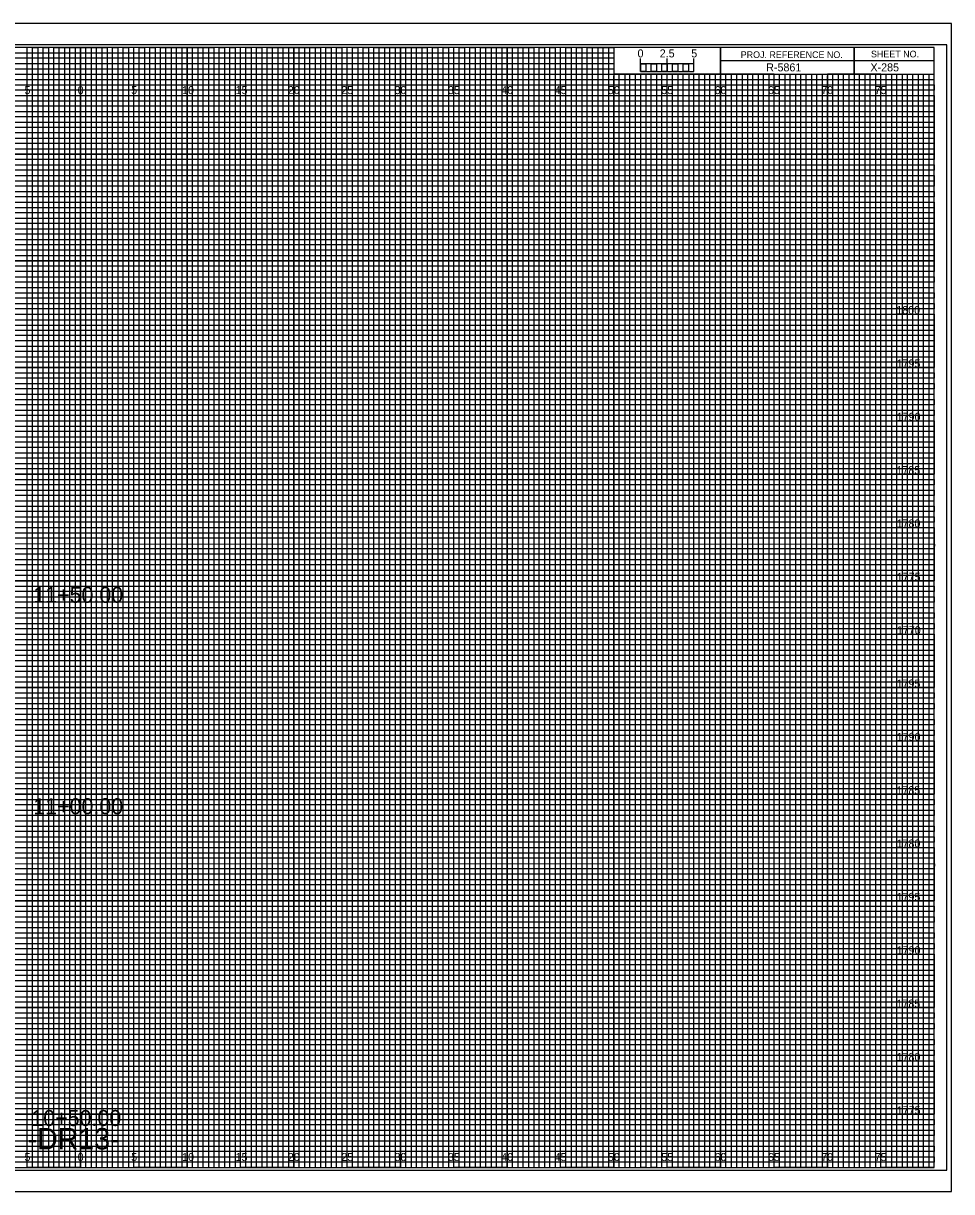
# Model space of a CAD drawing. Extents: x -7 to 162, y -2 to 107.
# Drawn here: x 74.6 to 161.7, y -2.3 to 107.3 of the extents above; entities that cross this region are included whole.
import ezdxf

# ---------------------------------------------------------------- set-up
doc = ezdxf.new("R2010")
doc.units = 0
for name, color, linetype in [('Prop XS Alignment Label', 7, 'Continuous'), ('Prop XS Bar Scale Labels', 7, 'Continuous'), ('Prop XS Elevation Labels', 7, 'Continuous'), ('Prop XS Offset Labels', 7, 'Continuous'), ('Prop XS Project Number', 7, 'Continuous'), ('Prop XS Sheet Number', 7, 'Continuous'), ('Prop XS Station Labels', 7, 'Continuous'), ('Sheet Cross Section CELL', 7, 'Continuous'), ('Sheet Cross Section Grid Major CELL', 7, 'Continuous'), ('Sheet Cross Section Grid Middle CELL', 7, 'Continuous'), ('Sheet Cross Section Grid Minor 1 CELL', 7, 'Continuous'), ('Sheet Cross Section Grid Minor 2 CELL', 7, 'Continuous'), ('Sheet Cross Section Scale CELL', 7, 'Continuous'), ('Sheet Cutting Line CELL', 7, 'Continuous'), ('Sheet DOT Grid CELL', 7, 'Continuous'), ('Sheet Plot Border Inside CELL', 7, 'Continuous'), ('Sheet Plot Border Outside CELL', 7, 'Continuous')]:
    doc.layers.add(name, color=color, linetype=linetype)

msp = doc.modelspace()

# ---------------------------------------------------------------- linework, layer by layer
at = {"layer": 'Sheet Cross Section CELL'}
for p, q in [((152.5, 105), (152.5, 102.5)), ((152.5, 102.5), (152.5, 105)), ((160, 103.75), (140, 103.75)), ((140, 103.75), (140, 102.5)), ((140, 102.5), (160, 102.5))]:
    msp.add_line(p, q, dxfattribs=at)
for points in [[(160, 105), (0, 105), (0, 0), (160, 0)], [(140, 105), (130, 105), (130, 102.52), (140, 102.52)], [(160, 105), (140, 105), (140, 102.5), (160, 102.5)]]:
    msp.add_lwpolyline(points, close=True, dxfattribs=at)
at = {"layer": 'Sheet Cross Section Grid Major CELL'}
for p, q in [((75, 105), (70, 105)), ((75, 0), (75, 105)), ((85, 105), (80, 105)), ((80, 105), (80, 0)), ((85, 0), (85, 105)), ((95, 105), (90, 105)), ((90, 105), (90, 0)), ((95, 0), (95, 105)), ((105, 105), (100, 105)), ((100, 105), (100, 0)), ((105, 0), (105, 105)), ((115, 105), (110, 105)), ((110, 105), (110, 0)), ((115, 0), (115, 105)), ((125, 105), (120, 105)), ((120, 105), (120, 0)), ((125, 0), (125, 105)), ((130, 105), (130, 0)), ((135, 0), (135, 102.5)), ((145, 102.5), (140, 102.5)), ((140, 102.5), (140, 0)), ((145, 0), (145, 102.5)), ((155, 102.5), (150, 102.5)), ((150, 102.5), (150, 0)), ((155, 0), (155, 102.5)), ((80, 0), (75, 0)), ((90, 0), (85, 0)), ((100, 0), (95, 0)), ((110, 0), (105, 0)), ((120, 0), (115, 0)), ((130, 0), (125, 0)), ((140, 0), (135, 0)), ((150, 0), (145, 0)), ((160, 0), (155, 0)), ((160, 0), (160, 0))]:
    msp.add_line(p, q, dxfattribs=at)
for points in [[(0, 100), (160, 100), (160, 95), (0, 95)], [(0, 90), (160, 90), (160, 85), (0, 85)], [(0, 80), (160, 80), (160, 75), (0, 75)], [(0, 70), (160, 70), (160, 65), (0, 65)], [(0, 60), (160, 60), (160, 55), (0, 55)], [(0, 50), (160, 50), (160, 45), (0, 45)], [(0, 40), (160, 40), (160, 35), (0, 35)], [(0, 30), (160, 30), (160, 25), (0, 25)], [(0, 20), (160, 20), (160, 15), (0, 15)], [(0, 10), (160, 10), (160, 5), (0, 5)]]:
    msp.add_lwpolyline(points, dxfattribs=at)
at = {"layer": 'Sheet Cross Section Grid Middle CELL'}
for points in [[(72.5, 0), (77.5, 0), (77.5, 105), (82.5, 105), (82.5, 0), (87.5, 0), (87.5, 105), (92.5, 105), (92.5, 0), (97.5, 0), (97.5, 105), (102.5, 105), (102.5, 0), (107.5, 0), (107.5, 105), (112.5, 105), (112.5, 0), (117.5, 0), (117.5, 105), (122.5, 105), (122.5, 0), (127.5, 0), (127.5, 105), (129.97, 105), (130, 105), (130, 102.5), (132.5, 102.5), (132.5, 0), (137.5, 0), (137.5, 102.5), (142.5, 102.5), (142.5, 0), (147.5, 0), (147.5, 102.5), (152.5, 102.5), (152.5, 0), (157.5, 0), (157.5, 102.5)], [(0, 102.5), (137.5, 102.5)], [(0, 92.5), (160, 92.5), (160, 97.5), (0, 97.5)], [(0, 82.5), (160, 82.5), (160, 87.5), (0, 87.5)], [(0, 72.5), (160, 72.5), (160, 77.5), (0, 77.5)], [(0, 62.5), (160, 62.5), (160, 67.5), (0, 67.5)], [(0, 52.5), (160, 52.5), (160, 57.5), (0, 57.5)], [(0, 42.5), (160, 42.5), (160, 47.5), (0, 47.5)], [(0, 32.5), (160, 32.5), (160, 37.5), (0, 37.5)], [(0, 22.5), (160, 22.5), (160, 27.5), (0, 27.5)], [(0, 12.5), (160, 12.5), (160, 17.5), (0, 17.5)], [(0, 2.5), (160, 2.5), (160, 7.5), (0, 7.5)]]:
    msp.add_lwpolyline(points, dxfattribs=at)
at = {"layer": 'Sheet Cross Section Grid Minor 1 CELL'}
for p, q in [((0, 104.5), (130, 104.5)), ((130, 104.5), (130, 103.99)), ((130, 103.99), (0, 103.99)), ((0, 103.5), (130, 103.5)), ((130, 102.95), (0, 102.95)), ((130, 103.5), (130, 102.95)), ((0, 102), (160, 102))]:
    msp.add_line(p, q, dxfattribs=at)
for points in [[(0, 101.5), (135, 101.5), (160, 101.5), (160, 101), (0, 101)], [(0, 100.5), (160, 100.5), (160, 99.5), (0, 99.5)], [(0, 99), (160, 99), (160, 98.5), (0, 98.49)], [(0, 98), (160, 98), (160, 97), (0, 97)], [(0, 96.5), (160, 96.5), (160, 96), (0, 96)], [(0, 95.5), (160, 95.5), (160, 94.5), (0, 94.5)], [(0, 94), (160, 94), (160, 93.5), (0, 93.5)], [(0, 93), (160, 93), (160, 92), (0, 92)], [(0, 91.5), (160, 91.5), (160, 91), (0, 91)], [(0, 90.5), (160, 90.5), (160, 89.5), (0, 89.5)], [(0, 89), (160, 89), (160, 88.5), (0, 88.5)], [(0, 88), (160, 88), (160, 86.98), (160, 86.5), (160, 86), (0, 86)], [(0, 87), (160, 87), (160, 86.5), (0, 86.5)], [(0, 85.5), (160, 85.5), (160, 84.5), (0, 84.52)], [(0, 84.52), (160, 84.5), (160, 84), (0, 84)], [(0, 83.5), (160, 83.5), (160, 83), (0, 83)], [(0, 82), (160, 82), (160, 81.5), (0, 81.5)], [(0, 81), (160, 81), (160, 80.5), (0, 80.5)], [(-0.04, 79.45), (160, 79.45), (160, 78.94), (-0.04, 78.94)], [(0, 78.5), (160, 78.5), (160, 78), (0, 78)], [(0, 77), (160, 77), (160, 76.5), (0, 76.5)], [(0, 76), (160, 76), (160, 75.5), (0, 75.5)], [(0, 74.5), (160, 74.5), (160, 74), (0, 74)], [(0, 73.5), (160, 73.5), (160, 73), (0, 73)], [(0, 72), (160, 72), (160, 71.5), (0, 71.5)], [(0, 71), (160, 71), (160, 70.5), (0, 70.5)], [(0, 69.5), (160, 69.5), (160, 68.99), (0, 69)], [(0, 68.5), (160, 68.5), (160, 68), (0, 68)], [(0, 67), (160, 67), (160, 66.5), (0, 66.5)], [(0, 66), (160, 66), (160, 65.5), (0, 65.5)], [(0, 64.5), (160, 64.5), (160, 64), (0, 64)], [(0, 63.5), (160, 63.5), (160, 63), (0, 63)], [(0, 62), (160, 62), (160, 61.5), (0, 61.5)], [(0, 61), (160, 61), (160, 60.5), (0, 60.5)], [(0, 59.5), (160, 59.5), (160, 59), (0, 59)], [(0, 58.5), (160.03, 58.45), (160, 58), (0, 58)], [(0, 57), (160, 57), (160, 56.5), (0, 56.5)], [(0, 56), (160, 56), (160, 55.5), (0, 55.5)], [(0, 54.5), (160, 54.5), (160, 54), (0, 54)], [(0, 53.5), (160, 53.5), (160, 53), (0, 53)], [(0, 52), (160, 52), (160, 51.5), (0, 51.5)], [(0, 51), (160, 51), (160, 50.5), (0, 50.5)], [(0, 49.5), (160, 49.5), (160, 49), (0, 49)], [(0, 48.5), (160, 48.5), (160, 48), (0, 48)], [(0, 47), (160, 47), (160, 46.5), (0, 46.5)], [(0, 46), (160, 46), (160, 45.5), (0, 45.5)], [(0, 44.5), (160, 44.5), (160, 44), (0, 44)], [(0, 43.5), (160, 43.5), (160, 43), (0, 43)], [(0, 42), (160, 42), (160, 41.5), (0, 41.5)], [(0, 41), (160, 41), (160, 40.5), (0, 40.5)], [(0, 39.5), (160, 39.5), (160, 38.99), (0, 39)], [(0, 38.5), (160, 38.5), (160, 38), (0, 38)], [(0, 37), (160, 37), (160, 36.5), (0, 36.5)], [(0, 36), (160, 36), (160, 35.5), (0, 35.5)], [(0, 34.5), (160, 34.5), (160, 34), (0, 34)], [(0, 33.5), (160, 33.5), (160, 33), (0, 33)], [(0, 32), (160, 32), (160, 31.5), (0, 31.5)], [(0, 31), (160, 31), (160, 30.5), (0, 30.5)], [(0, 29.5), (160, 29.5), (160, 29), (0, 29)], [(0, 28.5), (160.03, 28.46), (160, 28), (0, 28)], [(0, 27), (160, 27), (160, 26.5), (0, 26.5)], [(0, 26), (160, 26), (160, 25.5), (0, 25.5)], [(0, 24.5), (160, 24.5), (160, 24), (0, 24)], [(0, 23.5), (160, 23.5), (160, 23), (0, 23)], [(0, 22), (160, 22), (160, 21.5), (0, 21.5)], [(0, 21), (160, 21), (160, 20.5), (0, 20.5)], [(0, 19.5), (160, 19.5), (160, 19), (0, 19)], [(0, 18.5), (160, 18.5), (160, 18), (0, 18)], [(0, 17), (160, 17), (160, 16.5), (0, 16.5)], [(0, 16), (160, 16), (160, 15.5), (0, 15.5)], [(0, 14.5), (160, 14.5), (160, 14), (0, 14)], [(0, 13.5), (160, 13.5), (160, 13), (0, 13)], [(0, 12), (160, 12), (160, 11.5), (0, 11.5)], [(0, 11), (160, 11), (160, 10.5), (0, 10.5)], [(0, 9.5), (160, 9.5), (160, 9), (0, 9)], [(0, 8.5), (160, 8.5), (160, 8), (0, 8)], [(0, 7), (160, 7), (160, 6.5), (0, 6.5)], [(0, 6), (160, 6), (160, 5.5), (0, 5.5)], [(0, 4.5), (160, 4.5), (160, 4), (0, 4)], [(0, 3.5), (160, 3.5), (160, 3), (0, 3)], [(0, 2), (160, 2), (160, 1.5), (0, 1.5)], [(0, 1), (160, 1), (160, 0.5), (0, 0.5)]]:
    msp.add_lwpolyline(points, dxfattribs=at)
at = {"layer": 'Sheet Cross Section Grid Minor 2 CELL'}
for p, q in [((133.5, 102.5), (133, 102.5)), ((133, 102.5), (133, 0)), ((133.5, 0), (133.5, 102.5)), ((134.5, 102.5), (134, 102.5)), ((134, 102.5), (134, 0)), ((134.5, 0), (134.5, 102.5)), ((133, 0), (132.5, 0)), ((134, 0), (133.5, 0))]:
    msp.add_line(p, q, dxfattribs=at)
for points in [[(75, 0), (75.5, 0), (75.5, 105), (76, 105), (76, 0)], [(76, 0), (76.5, 0), (76.5, 105), (77, 105), (77, 0)], [(77.5, 0), (78, 0), (78, 105), (78.5, 105), (78.5, 0)], [(78.5, 0), (79, 0), (79, 105), (79.5, 105), (79.5, 0)], [(80, 0), (80.5, 0), (80.5, 105), (81, 105), (81, 0)], [(81, 0), (81.5, 0), (81.5, 105), (82, 105), (82, 0)], [(82.5, 0), (83, 0), (83, 105), (83.5, 105), (83.5, 0)], [(83.5, 0), (84, 0), (84, 105), (84.5, 105), (84.5, 0)], [(85, 0), (85.5, 0), (85.5, 105), (86, 105), (86, 0)], [(86, 0), (86.5, 0), (86.5, 105), (87, 105), (87, 0)], [(87.5, 0), (88, 0), (88, 105), (88.5, 105), (88.5, 0)], [(88.5, 0), (89, 0), (89, 105), (89.5, 105), (89.5, 0)], [(90, 0), (90.5, 0), (90.5, 105), (91, 105), (91, 0)], [(91, 0), (91.5, 0), (91.5, 105), (92, 105), (92, 0)], [(92.5, 0), (93, 0), (93, 105), (93.5, 105), (93.5, 0)], [(93.5, 0), (94, 0), (94, 105), (94.5, 105), (94.5, 0)], [(95, 0), (95.5, 0), (95.5, 105), (96, 105), (96, 0)], [(96, 0), (96.5, 0), (96.5, 105), (97, 105), (97, 0)], [(97.5, 0), (98, 0), (98, 105), (98.5, 105), (98.5, 0)], [(98.5, 0), (99, 0), (99, 105), (99.5, 105), (99.5, 0)], [(100, 0), (100.5, 0), (100.5, 105), (101, 105), (101, 0)], [(101, 0), (101.5, 0), (101.5, 105), (102, 105), (102, 0)], [(102.5, 0), (103, 0), (103, 105), (103.5, 105), (103.5, 0)], [(103.5, 0), (104, 0), (104, 105), (104.5, 105), (104.5, 0)], [(105, 0), (105.5, 0), (105.5, 105), (106, 105), (106, 0)], [(106, 0), (106.5, 0), (106.5, 105), (107, 105), (107, 0)], [(107.5, 0), (108, 0), (108, 105), (108.5, 105), (108.5, 0)], [(108.5, 0), (109, 0), (109, 105), (109.5, 105), (109.5, 0)], [(110, 0), (110.5, 0), (110.5, 105), (111, 105), (111, 0)], [(111, 0), (111.5, 0), (111.5, 105), (112, 105), (112, 0)], [(112.5, 0), (113, 0), (113, 105), (113.5, 105), (113.5, 0)], [(113.5, 0), (114, 0), (114, 105), (114.5, 105), (114.5, 0)], [(115, 0), (115.5, 0), (115.5, 105), (116, 105), (116, 0)], [(116, 0), (116.5, 0), (116.5, 105), (117, 105), (117, 0)], [(117.5, 0), (118, 0), (118, 105), (118.5, 105), (118.5, 0)], [(118.5, 0), (119, 0), (119, 105), (119.5, 105), (119.5, 0)], [(120, 0), (120.5, 0), (120.5, 105), (121, 105), (121, 0)], [(121, 0), (121.5, 0), (121.5, 105), (122, 105), (122, 0)], [(122.5, 0), (123, 0), (123, 105), (123.5, 105), (123.5, 0)], [(123.5, 0), (124, 0), (124, 105), (124.5, 105), (124.5, 0)], [(125, 0), (125.5, 0), (125.5, 105), (126, 105), (126, 0)], [(126, 0), (126.5, 0), (126.5, 105), (127, 105), (127, 0)], [(127.5, 0), (128, 0), (128, 105), (128.5, 105), (128.5, 0)], [(128.5, 0), (129, 0), (129, 105), (129.5, 105), (129.5, 0)], [(130, 0), (130.5, 0), (130.5, 102.5), (131.01, 102.5), (131.01, 0)], [(131, 0), (131.5, 0), (131.5, 102.5), (132, 102.5), (132, 0)], [(135, 0), (135.49, 0), (135.49, 102.5), (136, 102.5), (136, 0)], [(136, 0), (136.5, 0), (136.5, 102.5), (137.03, 102.5), (137.03, 0)], [(137.5, 0), (138, 0), (138, 102.5), (138.5, 102.5), (138.5, 0)], [(138.5, 0), (139, 0), (139, 102.5), (139.5, 102.5), (139.5, 0)], [(140, 0), (140.5, 0), (140.5, 102.5), (141, 102.5), (141, 0)], [(141, 0), (141.5, 0), (141.5, 102.5), (142, 102.5), (142, 0)], [(142.5, 0), (143, 0), (143, 102.5), (143.5, 102.5), (143.5, 0)], [(143.5, 0), (144, 0), (144, 102.5), (144.5, 102.5), (144.5, 0)], [(145, 0), (145.5, 0), (145.5, 102.5), (146, 102.5), (146, 0)], [(146, 0), (146.5, 0), (146.5, 102.5), (147, 102.5), (147, 0)], [(147.5, 0), (148, 0), (148, 102.5), (148.5, 102.5), (148.5, 0)], [(148.5, 0), (149, 0), (149, 102.5), (149.5, 102.5), (149.5, 0)], [(150, 0), (150.5, 0), (150.5, 102.5), (151, 102.5), (151, 0)], [(151, 0), (151.5, 0), (151.5, 102.5), (152, 102.5), (152, 0)], [(152.5, 0), (153, 0), (153, 102.5), (153.5, 102.5), (153.5, 0)], [(153.5, 0), (154, 0), (154, 102.5), (154.5, 102.5), (154.5, 0)], [(155, 0), (155.5, 0), (155.5, 102.5), (156, 102.5), (156, 0)], [(156, 0), (156.5, 0), (156.5, 102.5), (157, 102.5), (157, 0)], [(157.5, 0), (158, 0), (158, 102.5), (158.5, 102.5), (158.5, 0)], [(158.5, 0), (159, 0), (159, 102.5), (159.5, 102.5), (159.5, 0)]]:
    msp.add_lwpolyline(points, dxfattribs=at)
at = {"layer": 'Sheet Cross Section Scale CELL'}
for p, q in [((132.5, 102.75), (132.5, 103.95)), ((132.5, 103.45), (132.5, 103.95)), ((135, 102.75), (135, 103.95)), ((137.5, 102.75), (137.5, 103.95)), ((137.5, 103.45), (137.5, 103.95))]:
    msp.add_line(p, q, dxfattribs=at)
for points in [[(137.5, 103.45), (132.5, 103.45), (132.5, 102.75), (137.5, 102.75)], [(132.5, 103.45), (133, 103.45), (133, 102.75), (132.5, 102.75)], [(133.5, 103.45), (134, 103.45), (134, 102.75), (133.5, 102.75)], [(134.5, 103.45), (135, 103.45), (135, 102.75), (134.5, 102.75)], [(135.5, 103.45), (136, 103.45), (136, 102.75), (135.5, 102.75)], [(136.5, 103.45), (137, 103.45), (137, 102.75), (136.5, 102.75)]]:
    msp.add_lwpolyline(points, close=True, dxfattribs=at)
at = {"layer": 'Sheet Cutting Line CELL'}
for p, q in [((161.65, 107.25), (-6.7, 107.25)), ((-6.7, -2.25), (161.65, -2.25))]:
    msp.add_line(p, q, dxfattribs=at)
at = {"layer": 'Sheet DOT Grid CELL'}
for p, q in [((75, 0), (75, 105)), ((80, 0), (80, 105)), ((85, 0), (85, 105)), ((90, 0), (90, 105)), ((95, 0), (95, 105)), ((100, 0), (100, 105)), ((105, 0), (105, 105)), ((110, 0), (110, 105)), ((115, 0), (115, 105)), ((120, 0), (120, 105)), ((125, 0), (125, 105)), ((130, 0), (130, 102.34)), ((135, 0), (135, 102.34)), ((140, 0), (140, 102.34)), ((145, 0), (145, 102.34)), ((150, 0), (150, 102.34)), ((155, 0), (155, 102.34)), ((0, 100), (160, 100)), ((0, 95), (160, 95)), ((0, 90), (160, 90)), ((0, 85), (160, 85)), ((0, 80), (160, 80)), ((0, 75), (160, 75)), ((0, 70), (160, 70)), ((0, 65), (160, 65)), ((0, 60), (160, 60)), ((0, 55), (160, 55)), ((0, 50), (160, 50)), ((0, 45), (160, 45)), ((0, 40), (160, 40)), ((0, 35), (160, 35)), ((0, 30), (160, 30)), ((0, 25), (160, 25)), ((0, 20), (160, 20)), ((0, 15), (160, 15)), ((0, 10), (160, 10)), ((0, 5), (160, 5))]:
    msp.add_line(p, q, dxfattribs=at)
at = {"layer": 'Sheet Plot Border Inside CELL'}
msp.add_lwpolyline([(-5.4, -0.25), (161.2, -0.25), (161.2, 105.25), (-5.4, 105.25)], close=True, dxfattribs=at)
at = {"layer": 'Sheet Plot Border Outside CELL'}
msp.add_lwpolyline([(-6.7, -2.25), (161.65, -2.25), (161.65, 107.25), (-6.7, 107.25)], close=True, dxfattribs=at)

# ---------------------------------------------------------------- texts
at = {"layer": 'Prop XS Alignment Label'}
msp.add_text('-DR13-', height=2, dxfattribs=at).set_placement((75.04, 1.71))
at = {"layer": 'Prop XS Bar Scale Labels'}
for s, p in [('2.5', (134.29, 104.06)), ('5', (137.24, 104.06))]:
    msp.add_text(s, height=0.75, dxfattribs=at).set_placement(p)
at = {"layer": 'Prop XS Elevation Labels'}
for s, p in [('1800', (156.46, 80)), ('1795', (156.49, 75)), ('1790', (156.5, 70)), ('1785', (156.48, 65)), ('1780', (156.49, 60)), ('1775', (156.51, 55)), ('1770', (156.52, 50)), ('1795', (156.49, 45)), ('1790', (156.5, 40)), ('1785', (156.48, 35)), ('1780', (156.49, 30)), ('1795', (156.49, 25)), ('1790', (156.5, 20)), ('1785', (156.48, 15)), ('1780', (156.49, 10)), ('1775', (156.51, 5))]:
    msp.add_text(s, height=0.75, dxfattribs=at).set_placement(p)
at = {"layer": 'Prop XS Offset Labels'}
for s, p in [('5', (74.74, 100.62)), ('0', (79.73, 100.62)), ('0', (79.73, 100.62)), ('5', (84.74, 100.62)), ('10', (89.52, 100.62)), ('15', (94.53, 100.62)), ('20', (99.43, 100.62)), ('25', (104.44, 100.62)), ('30', (109.43, 100.62)), ('35', (114.44, 100.62)), ('40', (119.43, 100.62)), ('45', (124.44, 100.62)), ('50', (129.43, 100.62)), ('55', (134.44, 100.62)), ('60', (139.43, 100.62)), ('65', (144.44, 100.62)), ('70', (149.43, 100.62)), ('75', (154.44, 100.62)), ('5', (74.74, 0.62)), ('0', (79.73, 0.62)), ('0', (79.73, 0.62)), ('5', (84.74, 0.62)), ('10', (89.52, 0.62)), ('15', (94.53, 0.62)), ('20', (99.43, 0.62)), ('25', (104.44, 0.62)), ('30', (109.43, 0.62)), ('35', (114.44, 0.62)), ('40', (119.43, 0.62)), ('45', (124.44, 0.62)), ('50', (129.43, 0.62)), ('55', (134.44, 0.62)), ('60', (139.43, 0.62)), ('65', (144.44, 0.62)), ('70', (149.43, 0.62)), ('75', (154.44, 0.62))]:
    msp.add_text(s, height=0.75, dxfattribs=at).set_placement(p)
at = {"layer": 'Prop XS Project Number'}
msp.add_text('R-5861', height=0.75, dxfattribs=at).set_placement((144.27, 102.75))
at = {"layer": 'Prop XS Sheet Number'}
msp.add_text('X-285', height=0.75, dxfattribs=at).set_placement((154.04, 102.75))
at = {"layer": 'Prop XS Station Labels'}
for s, p in [('11+50.00', (75.57, 52.94)), ('11+00.00', (75.57, 33.12)), ('10+50.00', (75.39, 3.9))]:
    msp.add_text(s, height=1.5, dxfattribs=at).set_placement(p)
at = {"layer": 'Sheet Cross Section CELL'}
for s, p in [('PROJ. REFERENCE NO.', (141.88, 104)), ('SHEET NO.', (154.09, 104.06))]:
    msp.add_text(s, height=0.625, dxfattribs=at).set_placement(p)
at = {"layer": 'Sheet Cross Section Scale CELL'}
msp.add_text('0', height=0.75, dxfattribs=at).set_placement((132.21, 104.06))

doc.saveas('drawing.dxf')
